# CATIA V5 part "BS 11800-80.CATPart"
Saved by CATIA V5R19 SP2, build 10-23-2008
Part number: BS 11800-80
Bounding box of the stored display mesh (mm): x -74.81 to 74.81, y -74.81 to 74.81, z 0 to 238
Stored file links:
  C:\Users\Bora\Desktop\3D Katı model\BS serisi\BS 11800\BS 11800-80.CATPart
  C:\Program Files\Dassault Systemes\B19\intel_a\reffiles\standard\MetricThickPitch.txt
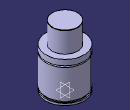
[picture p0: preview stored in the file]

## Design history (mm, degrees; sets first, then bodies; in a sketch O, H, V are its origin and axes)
Body1 (main body)
  Sketch1 on yz-plane, origin (0, 0, 0), H (0, 1, 0), V (0, 0, 1)
    point P1 (75, 135)
    point P2 (75, 130)
    point P5 (50, 237)
    point P7 (50, 237)
    point P12 (75, 130)
    point P13 (75, 135)
    arc A1 centre (75, 132.5) radius 2.5 from (75, 135) to (75, 130) ccw
    line L1 (75, 0) -> (75, 8)
    line L2 (50, 237) -> (50, 157)
    arc A2 centre (49, 237) radius 1 from (50, 237) to (49, 238) ccw
    line L3 (71, 15) -> (71, 8)
    line L4 (75, 15) -> (75, 130)
    line L5 (75, 135) -> (75, 157)
    line L6 (49, 238) -> (0, 238)
    point P15 (0, 238)
    line L7 (50, 157) -> (75, 157)
    line L8 (0, 0) -> (75, 0)
    line L9 (71, 15) -> (75, 15)
    line L10 (71, 8) -> (75, 8)
    coincidence: P15 V, P1 P13, P2 P12, P5 P7
    tangency: L6 A2
    horizontal: L7 H, L8 H, L9 H
    parallelism: L10 L7
  Shaft1: profile Sketch1, axis Sketch1.V, angle 360
  Sketch2 on face of Shaft1 from Sketch1.L8, origin (0, 0, 0), H (1, 0, 0), V (0, -1, 0)
    point P1 (50, 0)
    distance P1 V = 50
  Hole1: placed by Sketch2, at (50, 0, 0) direction (0, 0, 1), diameter 8.376, depth 12, threaded "M10", thread diameter 10, thread depth 12, pitch 1.5
  CircPattern1: of Hole1, instances 4, angular step 90, axis from xy-plane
